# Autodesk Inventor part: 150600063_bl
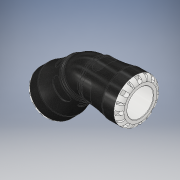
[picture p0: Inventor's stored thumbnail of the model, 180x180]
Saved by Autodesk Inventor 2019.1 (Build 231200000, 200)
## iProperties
Created: 2016-12
Part Number: 150600063_bl
Material: PVC-Piping
Description: PLASSON G-PLASS 45°  ELBOW 63-63
Document SubType Name: Modeling
Designer: KIM
Mass: 664.223 g
Surface Area: 733.008 cm^2
Volume: 474.445 cm^3
Density: 1.4 g/cm^3
Appearance: Black Cast
Author: KIM
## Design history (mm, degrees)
derived "150600.ipt"
feature "Solid1::150600.ipt" dims "ScaleForDerivedMember" = 10
tag "TaggingFeature1"
body "Solid1"
other parameters: "d1" = 39.9 [user parameter], "d2" = 63 [user parameter], "d3" = 78.75 [user parameter], "d4" = 103 [user parameter], "d8" = 87.55 [user parameter], "d13" = 9.7 [user parameter], "d14" = 9.7 [user parameter], "d15" = 0 [user parameter], "d17" = 360 deg [user parameter], "d19" = 8 deg [user parameter], "d20" = 1.26 [user parameter], "d21" = 1.26 [user parameter], "d22" = 8 deg [user parameter], "d24" = 0 [user parameter], "d26" = 360 deg [user parameter], "d33" = 10.3 [user parameter], "d43" = 80.34 [user parameter], "d51" = 1.03 [user parameter], "d54" = 22.05 [user parameter], "d55" = 13.86 [user parameter], "d57" = 19.012 [user parameter], "d58" = 0 [user parameter], "d74" = 0 [user parameter], "d77" = 5.25 [user parameter], "d78" = 95 [user parameter], "d82" = 1.26 [user parameter], "d115" = 360 deg [user parameter], "d207" = 90 deg [user parameter], "d228" = 18.7425 [user parameter], "d247" = 2.06 [user parameter], "d248" = 5.7 [user parameter], "d268" = 18.3855 [user parameter], "d269" = 5.51565 [user parameter], "d270" = 123 [user parameter], "d277" = 135 deg [user parameter], "d279" = 5.51565 [user parameter], "d280" = 135 deg [user parameter], "d281" = 0 [user parameter], "d282" = 0 [user parameter], "d_" = 63 [user parameter], "E_" = 103 [user parameter], "l_" = 95 [user parameter], "A_" = 123 [user parameter], "d9" = 12.125 [user parameter], "d11" = 103 [user parameter], "d12" = 78.75 [user parameter]
